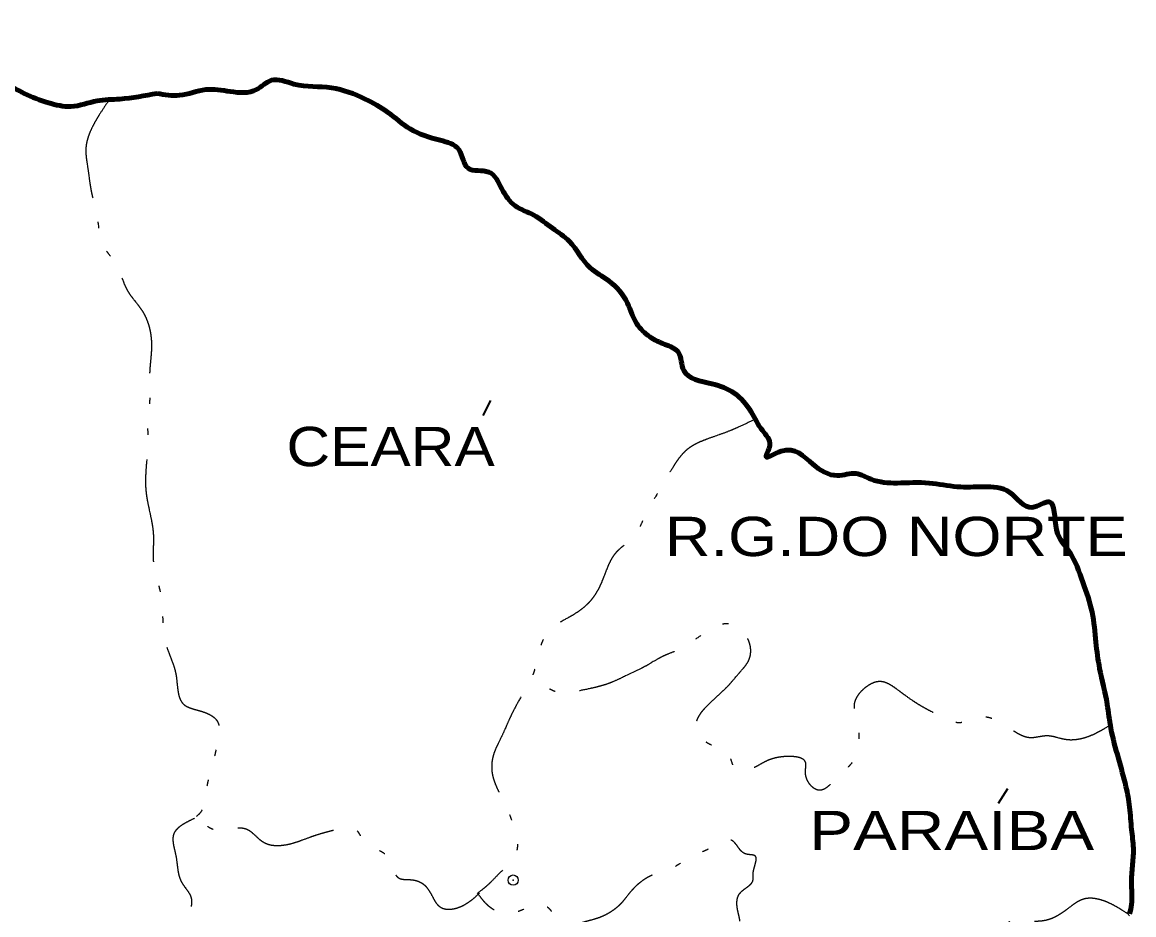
# Model space of a CAD drawing. Extents: x 512883 to 1063249, y 8784064 to 9081064.
# Drawn here: x 1001709 to 1034045, y 8999478 to 9025452 of the extents above; entities that cross this region are included whole.
import ezdxf

# ---------------------------------------------------------------- set-up
doc = ezdxf.new("R2010")
doc.units = 0
doc.header["$LTSCALE"] = 600
doc.header["$PDMODE"] = 32
doc.header["$PDSIZE"] = 300
doc.linetypes.add('DASH_DOUBLE_DOT', pattern=[9.2, 5, -1.2, 0.3, -1.2, 0.3, -1.2])
doc.layers.add('30', color=7, linetype='Continuous', lineweight=25)

msp = doc.modelspace()

# ---------------------------------------------------------------- linework, layer by layer
at = {"layer": '30', "lineweight": 35}
for p, q in [((1015118.6, 9014005.3), (1015336.7, 9014441.3)), ((1030108.9, 9002721.7), (1030381.5, 9003157.7))]:
    msp.add_line(p, q, dxfattribs=at)
at = {"layer": '30', "lineweight": 13}
msp.add_line((1033924.6, 8999451), (1033870.1, 8999505.6), dxfattribs=at)
at = {"layer": '30', "lineweight": 140}
for points in [[(996367.1, 9025452.4), (996476.1, 9025343.4), (997184.8, 9025234.4), (997784.4, 9024961.8), (998275, 9024852.8), (998056.9, 9024253.2), (998602, 9024144.2), (999365.2, 9023926.1), (1000400.9, 9023817.1), (1001218.5, 9023653.6), (1001763.6, 9023381), (1002472.3, 9023108.5), (1003126.4, 9022999.5), (1003889.5, 9023163), (1004543.7, 9023217.5), (1005633.9, 9023381)], [(1005633.9, 9023381), (1006288, 9023326.5), (1007051.1, 9023490), (1007759.8, 9023435.5), (1008522.9, 9023490), (1008959, 9023762.6), (1009613.1, 9023653.6), (1010703.3, 9023544.6), (1011684.5, 9023217.5), (1012338.6, 9022835.9), (1012992.7, 9022345.3), (1013864.9, 9022018.3), (1014410, 9021745.7), (1014682.6, 9021200.6), (1015282.2, 9021091.6), (1015663.7, 9020601), (1016045.3, 9020110.4), (1016590.4, 9019837.8), (1017135.5, 9019456.3), (1017626.1, 9019074.7), (1018225.7, 9018311.6), (1018770.8, 9017930), (1019315.9, 9017275.9), (1019588.5, 9016676.3), (1019970, 9016294.7), (1020406.1, 9016076.7), (1020787.7, 9015858.6), (1020951.2, 9015313.5), (1021768.9, 9014931.9), (1022423, 9014659.4), (1022913.6, 9014114.3), (1023240.7, 9013569.2), (1023458.7, 9013133.1), (1023349.7, 9012806), (1023785.8, 9012969.6), (1024712.4, 9012588), (1025421.1, 9012260.9), (1025966.2, 9012315.5), (1026402.2, 9012151.9), (1027165.4, 9012042.9), (1028092.1, 9012042.9), (1028909.7, 9011933.9), (1029672.8, 9011933.9), (1030436, 9011770.3), (1031090.1, 9011334.3), (1031580.7, 9011497.8), (1031798.8, 9010680.1), (1032180.3, 9010026), (1032561.9, 9009153.9), (1032834.4, 9008281.7), (1032943.5, 9007409.5), (1033052.5, 9006646.4), (1033270.5, 9005610.7), (1033379.5, 9004902.1), (1033597.6, 9004029.9), (1033815.6, 9003212.2), (1033924.6, 9002612.6), (1033979.2, 9001958.5), (1034033.7, 9001413.4), (1033979.2, 9000432.2), (1033979.2, 8999778.1), (1033924.6, 8999505.6)]]:
    msp.add_spline(points, degree=3, dxfattribs=at)
at = {"layer": '30', "linetype": 'DASH_DOUBLE_DOT'}
for points in [[(1004216.6, 9023163), (1003835, 9022563.4), (1003562.5, 9021800.2), (1003617, 9021200.6), (1003726, 9020492), (1003889.5, 9019783.3), (1004053.1, 9018965.7), (1004434.6, 9018420.6), (1004761.7, 9017657.5), (1005197.8, 9017057.8), (1005470.3, 9016076.7), (1005415.8, 9015259), (1005415.8, 9014441.3), (1005361.3, 9013841.7), (1005361.3, 9013242.1), (1005306.8, 9011824.9), (1005524.8, 9010516.6), (1005524.8, 9009753.5), (1005742.9, 9008772.3), (1005797.4, 9008063.7), (1005906.4, 9007300.5), (1006179, 9006482.9), (1006397, 9005610.7), (1006942.1, 9005392.7), (1007378.2, 9005120.1), (1007378.2, 9004411.5), (1007214.7, 9003757.3), (1007051.1, 9003048.7), (1006887.6, 9002449.1), (1006778.6, 9002340.1)], [(1023022.6, 9013896.2), (1022314, 9013569.2), (1021714.4, 9013351.1), (1021060.2, 9013024.1), (1020624.2, 9012479), (1020242.6, 9011824.9), (1019861, 9011170.7), (1019479.4, 9010462.1), (1018988.8, 9010026), (1018607.3, 9009262.9), (1018280.2, 9008663.3), (1017680.6, 9008172.7), (1017026.5, 9007736.6), (1016699.4, 9006973.5), (1016590.4, 9006537.4), (1016317.8, 9005992.3), (1015881.8, 9005174.6), (1015663.7, 9004684), (1015391.2, 9004029.9), (1015391.2, 9003539.3), (1015718.2, 9002776.2), (1016045.3, 9001904), (1016099.8, 9001358.9), (1015609.2, 9000704.8), (1015227.7, 9000323.2), (1014955.1, 9000105.2)], [(1033379.5, 9005011.1), (1032779.9, 9004684), (1032071.3, 9004575), (1031526.2, 9004684), (1031035.6, 9004629.5), (1030436, 9004902.1), (1029618.3, 9005229.1), (1028964.2, 9005065.6), (1028473.6, 9005229.1), (1027765, 9005610.7), (1027219.9, 9005992.3), (1026674.8, 9006264.8), (1026184.2, 9006046.8), (1025911.7, 9005610.7), (1026020.7, 9005011.1), (1026020.7, 9004411.5), (1025857.1, 9003920.9), (1025475.6, 9003539.3), (1024876, 9003103.2), (1024494.4, 9003593.8), (1024494.4, 9003920.9), (1023949.3, 9004084.4), (1023295.2, 9003920.9), (1022859.1, 9003702.8), (1022477.5, 9003702.8), (1022259.5, 9004138.9), (1022041.4, 9004302.5), (1021659.8, 9004466), (1021332.8, 9004847.6), (1022205, 9006101.3), (1022586.5, 9006537.4), (1022859.1, 9006918.9), (1022859.1, 9007409.5), (1022641, 9007736.6), (1022423, 9007900.1), (1021005.7, 9007300.5), (1020678.7, 9007137), (1020406.1, 9007028), (1019915.5, 9006755.4), (1019261.4, 9006428.3), (1018770.8, 9006210.3), (1017898.7, 9005992.3), (1017353.6, 9005937.8), (1016972, 9006101.3), (1016535.9, 9006537.4)], [(1006724.1, 9002285.6), (1006506, 9002176.6), (1006124.5, 9001849.5), (1006179, 9001195.4), (1006342.5, 9000432.2), (1006615, 8999996.2), (1006342.5, 8999178.5), (1005906.4, 8998687.9), (1005088.8, 8997924.8), (1004053.1, 8997270.6), (1003289.9, 8996889.1), (1003017.4, 8996289.5), (1002908.3, 8996180.4)], [(1015009.6, 9000105.2), (1014355.5, 8999669.1), (1013919.4, 8999669.1), (1013483.3, 9000268.7), (1013047.2, 9000486.7), (1012665.7, 9000541.2), (1012447.6, 9001031.8), (1012066.1, 9001358.9), (1011684.5, 9001576.9), (1011411.9, 9001958.5), (1010866.8, 9001958.5), (1010103.7, 9001740.5), (1009449.6, 9001522.4), (1008740.9, 9001576.9), (1008250.3, 9001958.5), (1007650.7, 9001958.5), (1007269.2, 9001958.5), (1006833.1, 9002340.1)], [(1033870.1, 8999505.6), (1033161.5, 8999887.1), (1032616.4, 8999941.6), (1032071.3, 8999614.6), (1031580.7, 8999342), (1031090.1, 8999287.5), (1030490.5, 8999287.5), (1029999.9, 8999015), (1029236.8, 8998633.4), (1028855.2, 8998415.3), (1028310.1, 8998415.3), (1027819.5, 8998687.9), (1027328.9, 8998851.4), (1026729.3, 8998578.9), (1026184.2, 8998960.5), (1025748.1, 8999015), (1025366.5, 8998578.9), (1025094, 8998197.3), (1024766.9, 8997706.7), (1024439.9, 8997107.1), (1024003.8, 8996671), (1023676.7, 8996507.5), (1023186.1, 8996562), (1022913.6, 8996780), (1022750.1, 8997161.6), (1022695.6, 8997706.7), (1022477.5, 8998033.8), (1021986.9, 8998088.3), (1021877.9, 8998415.3), (1022314, 8998796.9), (1022586.5, 8999233), (1022532, 8999560.1), (1022586.5, 9000105.2), (1022968.1, 9000486.7), (1022968.1, 9000650.3), (1023022.6, 9001195.4), (1022750.1, 9001249.9), (1022368.5, 9001631.5), (1021714.4, 9001413.4), (1021114.8, 9001140.9), (1020569.7, 9000813.8), (1020079.1, 9000650.3), (1019370.4, 9000105.2), (1019152.4, 8999832.6), (1018498.3, 8999396.5), (1017953.2, 8999233), (1017353.6, 8999124), (1017081, 8999614.6), (1016753.9, 8999778.1), (1016099.8, 8999560.1), (1015445.7, 8999614.6), (1014955.1, 9000105.2)]]:
    msp.add_spline(points, degree=3, dxfattribs=at)
at = {"layer": '30'}
msp.add_point((1015990.8, 9000486.7), dxfattribs=at)

# ---------------------------------------------------------------- texts
for s, width, p in [('CEARA', 1.15, (1009395.1, 9012533.5)), ('R.G.DO NORTE', 1.2, (1020406.1, 9009917)), ('PARAIBA', 1.25, (1024603.4, 9001358.9))]:
    msp.add_text(s, height=1144, dxfattribs=dict(at, width=width)).set_placement(p)

doc.saveas('drawing.dxf')
